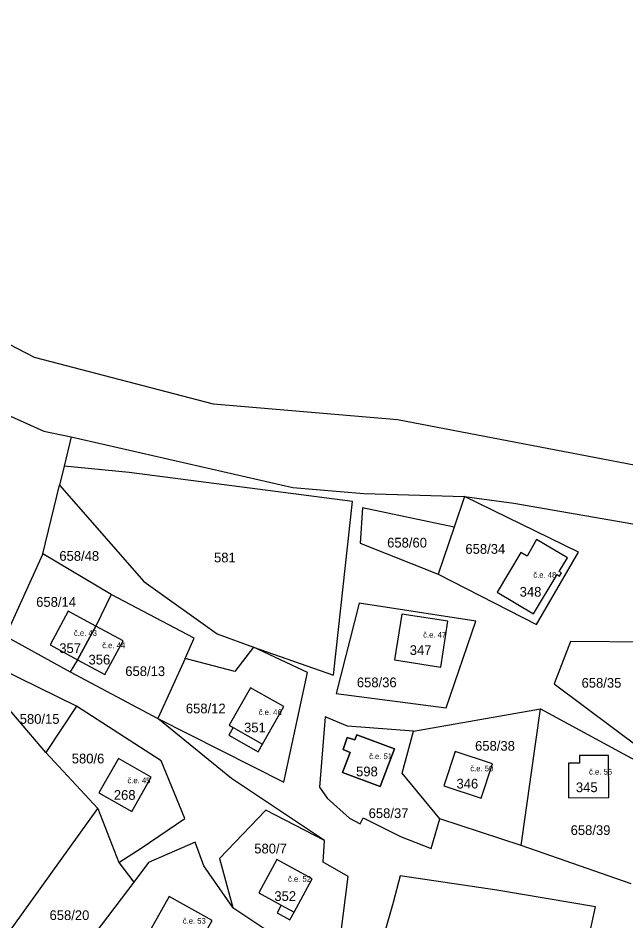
# Model space of a CAD drawing. Extents: x -887272 to -877616, y -1026687 to -1019819.
# Drawn here: x -883908.9 to -883802.7, y -1024093.2 to -1023935.4 of the extents above; entities that cross this region are included whole.
import ezdxf

# ---------------------------------------------------------------- set-up
doc = ezdxf.new("R2010")
doc.units = 0
for name, color, linetype in [('Definiční body', 7, 'Continuous'), ('Hranice parcel', 7, 'Continuous'), ('Parcelní čísla', 7, 'Continuous'), ('Polygon budovy', 7, 'Continuous'), ('Vnitřní kresba', 7, 'Continuous')]:
    doc.layers.add(name, color=color, linetype=linetype)

msp = doc.modelspace()

# ---------------------------------------------------------------- linework, layer by layer
at = {"layer": 'Hranice parcel'}
for p, q in [((-883899.62, -1024008.57), (-883900.86, -1024013.67)), ((-883900.86, -1024013.67), (-883901.68, -1024017.03)), ((-883904.58, -1024028.99), (-883901.68, -1024017.03)), ((-883832.76, -1024024.32), (-883835.54, -1024032.54)), ((-883904.58, -1024028.99), (-883911.13, -1024043.4)), ((-883892.65, -1024036.09), (-883904.58, -1024028.99)), ((-883892.65, -1024036.09), (-883895.35, -1024041.64)), ((-883895.35, -1024041.64), (-883898.54, -1024047.52)), ((-883911.13, -1024043.4), (-883899.81, -1024049.6)), ((-883898.54, -1024047.52), (-883899.81, -1024049.6)), ((-883879.74, -1024047.28), (-883884.47, -1024057.79)), ((-883898.73, -1024055.6), (-883911.85, -1024049.13)), ((-883899.81, -1024049.6), (-883884.47, -1024057.79)), ((-883815.27, -1024051.72), (-883799.82, -1024063.26)), ((-883904.07, -1024063.74), (-883912, -1024054.42)), ((-883898.73, -1024055.6), (-883904.07, -1024063.74)), ((-883839.82, -1024059.97), (-883817.65, -1024056.09)), ((-883821.04, -1024079.95), (-883817.65, -1024056.09)), ((-883817.65, -1024056.09), (-883798.98, -1024066.23)), ((-883904.07, -1024063.74), (-883895, -1024073.52)), ((-883911.25, -1024096.23), (-883895, -1024073.52)), ((-883895, -1024073.52), (-883891.31, -1024082.96)), ((-883821.04, -1024079.95), (-883835.23, -1024075.29)), ((-883801.81, -1024086.66), (-883821.04, -1024079.95)), ((-883891.31, -1024082.96), (-883888.71, -1024086.37)), ((-883886.12, -1024082.95), (-883888.71, -1024086.37)), ((-883888.71, -1024086.37), (-883902.86, -1024105.05)), ((-883871.37, -1024090.78), (-883864.73, -1024095.24))]:
    msp.add_line(p, q, dxfattribs=at)
for points in [[(-883756.5, -1024023.04), (-883767.66, -1024020.24), (-883797.06, -1024014.34), (-883842.62, -1024005.56), (-883874.8, -1024002.84), (-883906.02, -1023994.68), (-883929.04, -1023982.78), (-884005.12, -1023932.5), (-884033.98, -1023912.56), (-884080.28, -1023877.34), (-884136.58, -1023830.48), (-884162.3, -1023804.42), (-884180.14, -1023781.6), (-884204.86, -1023736.02), (-884224.62, -1023704.92), (-884247.24, -1023674.52), (-884253.66, -1023666.34), (-884254.22, -1023665.64)], [(-883913.13, -1024003.65), (-883904.38, -1024007.55), (-883899.62, -1024008.57)], [(-883899.62, -1024008.57), (-883860.9, -1024017.44), (-883848.52, -1024018.46), (-883830.95, -1024018.96), (-883822.3, -1024020.14), (-883798.84, -1024024.24), (-883786.49, -1024027.54)], [(-883867.76, -1024045.3), (-883853.82, -1024050.22), (-883850.5, -1024019.86), (-883889.5, -1024014.8), (-883900.86, -1024013.67)], [(-883901.68, -1024017.03), (-883886.96, -1024033.84), (-883874.14, -1024042.96), (-883867.76, -1024045.3)], [(-883835.54, -1024032.54), (-883818.36, -1024041.34), (-883811, -1024028.73), (-883830.95, -1024018.96), (-883832.76, -1024024.32)], [(-883832.76, -1024024.32), (-883848.72, -1024020.95), (-883849.18, -1024027.12), (-883835.54, -1024032.54)], [(-883814.31, -1024032.88), (-883813.98, -1024032.34), (-883814.4, -1024032.08), (-883812.92, -1024029.69), (-883818.33, -1024026.51), (-883820, -1024029.39), (-883821.08, -1024028.76), (-883825.2, -1024035.73), (-883818.87, -1024039.46), (-883814.73, -1024032.63), (-883814.31, -1024032.88)], [(-883879.74, -1024047.28), (-883878.15, -1024043.75), (-883892.65, -1024036.09)], [(-883853.32, -1024053.42), (-883834.12, -1024055.92), (-883828.96, -1024040.76), (-883849.32, -1024037.62), (-883853.32, -1024053.42)], [(-883895.35, -1024041.64), (-883900.14, -1024039.05), (-883903.32, -1024044.93), (-883898.54, -1024047.52)], [(-883843.14, -1024047.53), (-883835.09, -1024048.8), (-883833.83, -1024040.78), (-883841.88, -1024039.52), (-883843.14, -1024047.53)], [(-883898.54, -1024047.52), (-883893.75, -1024050.11), (-883890.57, -1024044.23), (-883895.35, -1024041.64)], [(-883790.11, -1024050.47), (-883793.99, -1024046.26), (-883798.72, -1024044.43), (-883812.43, -1024044.32), (-883815.27, -1024051.72)], [(-883884.47, -1024057.79), (-883862.5, -1024068.88), (-883858.34, -1024049.76), (-883867.76, -1024045.3)], [(-883867.76, -1024045.3), (-883871.06, -1024049.54), (-883879.74, -1024047.28)], [(-883866.19, -1024062.24), (-883862.5, -1024055.71), (-883868.29, -1024052.44), (-883872.04, -1024058.94), (-883871.33, -1024059.34), (-883872.1, -1024060.68), (-883866.95, -1024063.59), (-883866.19, -1024062.24)], [(-883891.31, -1024082.96), (-883887.41, -1024080.46), (-883879.76, -1024075.27), (-883883.92, -1024065.17), (-883898.73, -1024055.6)], [(-883839.82, -1024059.97), (-883851.38, -1024059.11), (-883855.27, -1024057.51), (-883856.27, -1024069.78), (-883854.92, -1024071.68), (-883851, -1024075.19)], [(-883855.39, -1024079.08), (-883871.6, -1024068.28), (-883884.47, -1024057.79)], [(-883851.41, -1024061.08), (-883850.08, -1024061.51), (-883849.74, -1024060.63), (-883843.18, -1024063.09), (-883845.65, -1024069.66), (-883852.21, -1024067.21), (-883850.9, -1024063.73), (-883852.14, -1024063.2), (-883851.41, -1024061.08)], [(-883835.23, -1024075.29), (-883841.84, -1024067.33), (-883839.82, -1024059.97)], [(-883832.57, -1024063.54), (-883834.56, -1024069.52), (-883828.01, -1024071.7), (-883826.02, -1024065.72), (-883832.57, -1024063.54)], [(-883889.05, -1024074.03), (-883885.63, -1024068.04), (-883891.36, -1024064.77), (-883894.78, -1024070.76), (-883889.05, -1024074.03)], [(-883805.74, -1024071.6), (-883805.76, -1024064.25), (-883810.86, -1024064.26), (-883810.86, -1024065.59), (-883812.76, -1024065.6), (-883812.74, -1024071.62), (-883805.74, -1024071.6)], [(-883855.39, -1024079.08), (-883865.64, -1024073.78), (-883873.75, -1024082.22), (-883871.37, -1024090.78)], [(-883851, -1024075.19), (-883849.14, -1024076.21), (-883848.6, -1024075.14), (-883842.11, -1024078.39)], [(-883842.11, -1024078.39), (-883836.75, -1024080.5), (-883835.23, -1024075.29)], [(-883871.37, -1024090.78), (-883876.44, -1024083.54), (-883877.98, -1024079.41), (-883886.12, -1024082.95)], [(-883853.46, -1024102.81), (-883851.26, -1024085.39), (-883855.59, -1024082.86), (-883855.39, -1024079.08)], [(-883863.67, -1024091.75), (-883861.44, -1024092.99), (-883860.69, -1024091.61), (-883857.51, -1024085.77), (-883863.7, -1024082.4), (-883866.88, -1024088.24), (-883862.93, -1024090.39), (-883863.67, -1024091.75)], [(-883827.31, -1024113.95), (-883822.48, -1024111.73), (-883815.82, -1024097.56), (-883809.04, -1024095.22), (-883808.05, -1024090.68), (-883825.31, -1024087.78), (-883842.14, -1024085.28), (-883843.37, -1024089.91), (-883848.46, -1024107.7)], [(-883878.22, -1024098.8), (-883875.02, -1024093.1), (-883882.54, -1024088.88), (-883885.74, -1024094.58), (-883878.22, -1024098.8)]]:
    msp.add_lwpolyline(points, dxfattribs=at)
at = {"layer": 'Polygon budovy'}
for points in [[(-883818.87, -1024039.46), (-883814.73, -1024032.63), (-883814.31, -1024032.88), (-883813.98, -1024032.34), (-883814.4, -1024032.08), (-883812.92, -1024029.69), (-883818.33, -1024026.51), (-883820, -1024029.39), (-883821.08, -1024028.76), (-883825.2, -1024035.73)], [(-883903.32, -1024044.93), (-883898.54, -1024047.52), (-883895.35, -1024041.64), (-883900.14, -1024039.05)], [(-883841.88, -1024039.52), (-883843.14, -1024047.53), (-883835.09, -1024048.8), (-883833.83, -1024040.78)], [(-883895.35, -1024041.64), (-883898.54, -1024047.52), (-883893.75, -1024050.11), (-883890.57, -1024044.23)], [(-883862.5, -1024055.71), (-883868.29, -1024052.44), (-883872.04, -1024058.94), (-883871.33, -1024059.34), (-883866.19, -1024062.24)], [(-883849.74, -1024060.63), (-883850.08, -1024061.51), (-883851.41, -1024061.08), (-883852.14, -1024063.2), (-883850.9, -1024063.73), (-883852.21, -1024067.21), (-883845.65, -1024069.66), (-883843.18, -1024063.09)], [(-883834.56, -1024069.52), (-883828.01, -1024071.7), (-883826.02, -1024065.72), (-883832.57, -1024063.54)], [(-883891.36, -1024064.77), (-883894.78, -1024070.76), (-883889.05, -1024074.03), (-883885.63, -1024068.04)], [(-883805.76, -1024064.25), (-883810.86, -1024064.26), (-883810.86, -1024065.59), (-883812.76, -1024065.6), (-883812.74, -1024071.62), (-883805.74, -1024071.6)], [(-883863.7, -1024082.4), (-883866.88, -1024088.24), (-883862.93, -1024090.39), (-883860.69, -1024091.61), (-883857.51, -1024085.77)], [(-883882.54, -1024088.88), (-883885.74, -1024094.58), (-883878.22, -1024098.8), (-883875.02, -1024093.1)]]:
    msp.add_lwpolyline(points, close=True, dxfattribs=at)
at = {"layer": 'Vnitřní kresba'}
for p, q in [((-883871.33, -1024059.34), (-883866.19, -1024062.24)), ((-883862.93, -1024090.39), (-883860.69, -1024091.61))]:
    msp.add_line(p, q, dxfattribs=at)

# ---------------------------------------------------------------- texts
at = {"layer": 'Definiční body'}
for s, p in [('č.e. 48', (-883818.91, -1024033.19)), ('č.e. 43', (-883899.15, -1024043.34)), ('č.e. 47', (-883838.15, -1024043.66)), ('č.e. 44', (-883894.22, -1024045.49)), ('č.e. 46', (-883866.87, -1024057.18)), ('č.e. 51', (-883847.59, -1024064.88)), ('č.e. 50', (-883829.92, -1024067.01)), ('č.e. 56', (-883809.17, -1024067.58)), ('č.e. 45', (-883889.8, -1024069.1)), ('č.e. 52', (-883861.75, -1024086.31)), ('č.e. 53', (-883880.14, -1024093.64))]:
    msp.add_text(s, height=1, dxfattribs=at).set_placement(p)
at = {"layer": 'Parcelní čísla'}
for s, p in [('658/60', (-883844.44, -1024027.9)), ('658/34', (-883830.77, -1024029)), ('658/48', (-883901.7, -1024030.22)), ('581', (-883874.68, -1024030.5)), ('348', (-883821.29, -1024036.49)), ('658/14', (-883905.74, -1024038.26)), ('357', (-883901.71, -1024046.34)), ('347', (-883840.49, -1024046.68)), ('356', (-883896.6, -1024048.34)), ('658/13', (-883890.18, -1024050.36)), ('658/36', (-883849.73, -1024052.32)), ('658/35', (-883810.48, -1024052.4)), ('658/12', (-883879.6, -1024056.88)), ('580/15', (-883908.62, -1024058.71)), ('351', (-883869.43, -1024060.2)), ('658/38', (-883829.08, -1024063.41)), ('580/6', (-883899.53, -1024065.63)), ('598', (-883849.87, -1024067.89)), ('346', (-883832.33, -1024070.01)), ('268', (-883892.18, -1024071.99)), ('345', (-883811.47, -1024070.65)), ('658/37', (-883847.67, -1024075.18)), ('658/39', (-883812.39, -1024078.14)), ('580/7', (-883867.65, -1024081.36)), ('352', (-883864.14, -1024089.66)), ('658/20', (-883903.41, -1024093))]:
    msp.add_text(s, height=1.7, dxfattribs=at).set_placement(p)

doc.saveas('drawing.dxf')
